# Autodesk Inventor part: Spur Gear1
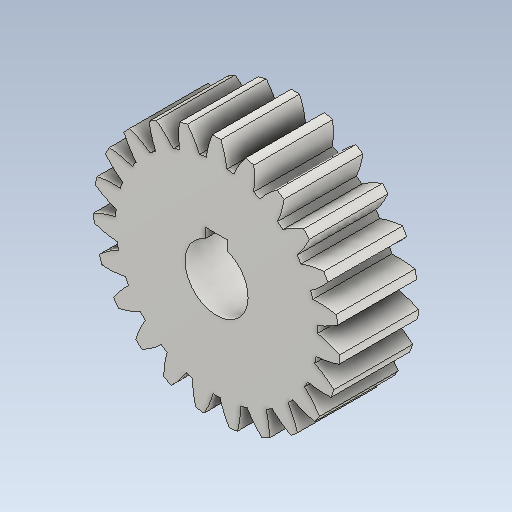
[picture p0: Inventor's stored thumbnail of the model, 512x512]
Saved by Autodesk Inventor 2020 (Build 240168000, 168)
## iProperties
CustomPartVersion: 1
Created: 2019-09
Part Number: Spur Gear1
Material: Steel
Document SubType Name: Modeling
Designer: user
Categories: <?xml version="1.0" encoding="UTF-16"?> <MemberInstance><Categories><FamilyTemplate><FamilyTemplateParameter ValueType="xs:double" Id="1" ObjectReferenceKey="da
Density: 7.85 g/cm^3
Appearance: Steel
Mass: 46.3267 g
Surface Area: 32.7024 cm^2
Volume: 5.9015 cm^3
Author: user
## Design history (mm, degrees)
sketch "Sketch1"
  geometry: C1 r 15.615 at (0, 0)
  constraints: 1 centre point
  dimensions: "d0" = 31.22933 diameter of C1 (= da_da)
extrude "Extrusion1" new body sketch "Sketch1" distance "d1" = 10 (= da_b); taper "d2" = 0 deg
workplane "Work Plane2"
sketch "Sketch2"
  geometry: C1 r 15.615 at (0, 0) reference; C2 r 14.457 at (0, 0)
  constraints: 1 centre point, 1 coincident
  dimensions: "d3" = 28.91429 diameter of C2 (= da_dw)
feature "Pitch Diameter" sketch "Sketch2" dims "d4" = 10, "d5" = 0
workplane "Work Plane8"
workplane "Work Plane9"
feature "Spur Gear" dims "da_b" = 10, "da_d" = 28.75, "da_aw" = 44, "da_da" = 31.22933, "da_df" = 25.625, "da_dw" = 28.91429, angle "da_beta" = 0 deg, "da_lefttooth" = 0, "da_righttooth" = 0
sketch "Sketch3"
  geometry: L1 (-1.432, 4.995)-(1.432, 4.995); L2 (1.432, 4.995)-(1.432, 3.735); L3 (-1.432, 3.735)-(-1.432, 4.995); A1 r 4 centre (0, 0) between (-1.432, 3.735) and (1.432, 3.735); 2 further points
  constraints: 6 end point, 2 point on circle, 1 centre point, 1 coincident, 1 horizontal, 1 midpoint, 1 parallel, 1 perpendicular, 1 vertical alignment
  dimensions: "d49" = 8 diameter of A1
extrude "Extrusion2" cut sketch "Sketch3" extent not by distance; stored distance "d50" = 0; taper "d51" = 0 deg
body "Solid1"
body "Srf1"
other parameters: "d16" = 44 (= da_aw), "d17" = 0, "d34" = 1.36591 (computed from da_z), "d39" = 0, "d41" = 0, "d43" = 44 (= da_aw), "d46" = 44 (= da_aw), "d47" = 0, "d48" = 0
